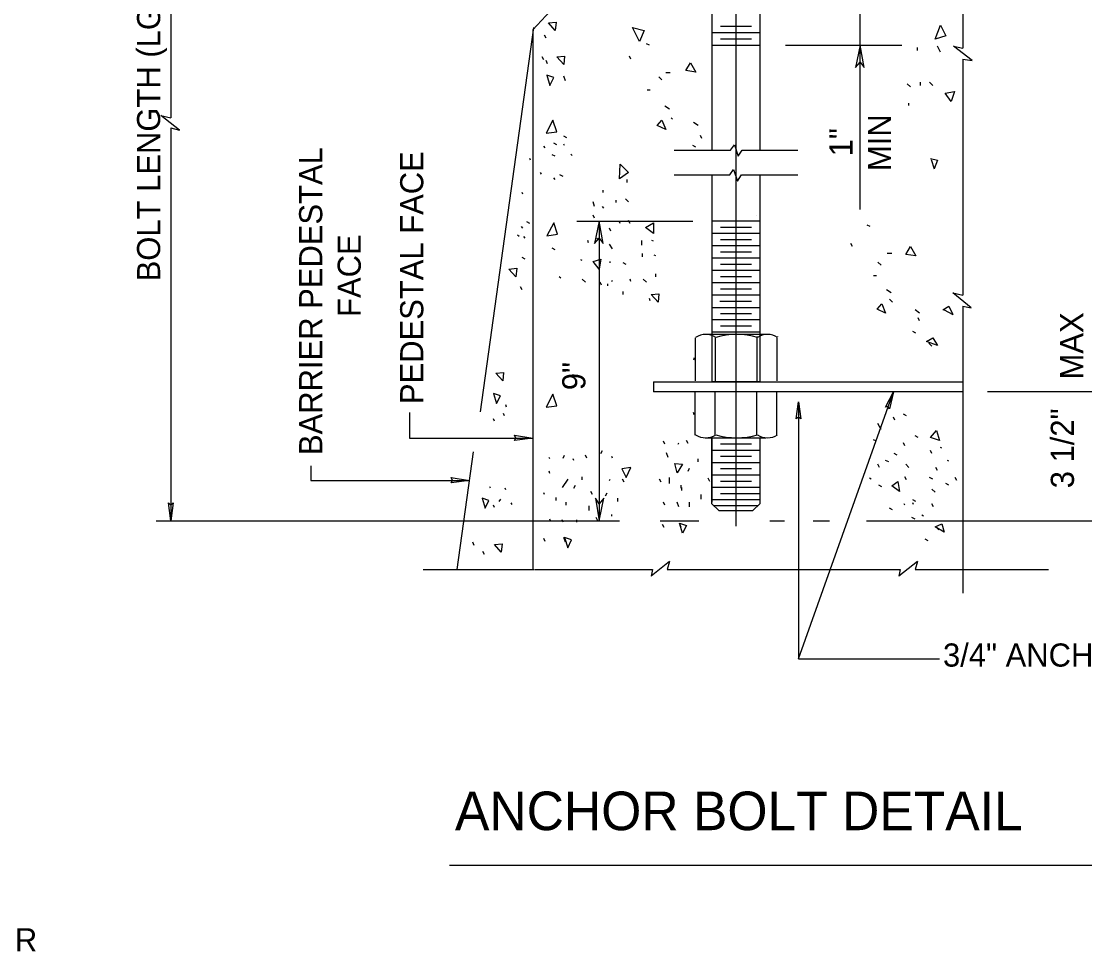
# Model space of a CAD drawing. Extents: x -3 to 26050223, y 0 to 12035012.
# Drawn here: x 15.59 to 27.07, y 26.48 to 36.52 of the extents above; entities that cross this region are included whole.
import ezdxf

# ---------------------------------------------------------------- set-up
doc = ezdxf.new("R2010")
doc.units = 0
for name, color, linetype in [('1', 7, 'Continuous'), ('2', 7, 'Continuous'), ('39', 7, 'Continuous')]:
    doc.layers.add(name, color=color, linetype=linetype)

msp = doc.modelspace()

# ---------------------------------------------------------------- linework, layer by layer
at = {"layer": '1'}
for p, q in [((23.308, 39.917), (23.308, 31.075)), ((23.05, 37.15), (23.05, 35.133)), ((23.567, 37.142), (23.567, 35.133)), ((21.117, 36.433), (21.35, 36.683)), ((20.55, 32.308), (21.125, 36.458)), ((21.117, 36.433), (21.117, 30.608)), ((23.533, 36.267), (23.533, 36.267)), ((23.05, 34.867), (23.05, 32.633)), ((23.567, 34.867), (23.567, 32.633)), ((22.867, 33.108), (22.867, 32.642)), ((23.633, 33.142), (22.975, 33.142)), ((23.633, 33.142), (22.975, 33.142)), ((23.083, 33.108), (23.083, 32.642)), ((23.533, 33.108), (23.533, 32.642)), ((23.75, 33.108), (23.75, 32.642)), ((22.417, 32.633), (22.417, 32.525)), ((22.417, 32.633), (25.758, 32.633)), ((25.758, 32.525), (22.417, 32.525)), ((22.867, 32.058), (22.867, 32.525)), ((23.083, 32.058), (23.083, 32.525)), ((23.533, 32.058), (23.533, 32.525)), ((23.75, 32.058), (23.75, 32.525)), ((23.633, 32.025), (22.975, 32.025)), ((23.633, 32.025), (22.975, 32.025)), ((23.05, 31.317), (23.05, 32.025)), ((23.567, 32.025), (23.567, 31.317)), ((20.3, 30.608), (20.475, 31.875)), ((23.05, 31.317), (23.125, 31.242)), ((23.542, 31.292), (23.075, 31.292)), ((23.125, 31.242), (23.492, 31.242)), ((23.567, 31.317), (23.492, 31.242)), ((20.217, 27.413), (27.25, 27.413))]:
    msp.add_line(p, q, dxfattribs=at)
for points in [[(24.65, 36.267), (24.6, 36.025), (24.65, 36.083), (24.692, 36.025)], [(21.833, 34.367), (21.783, 34.125), (21.833, 34.183), (21.875, 34.125)], [(21.833, 34.367), (21.783, 34.125), (21.833, 34.183), (21.875, 34.125)], [(20.933, 32.025), (20.917, 32.058), (21.117, 32.025), (20.917, 32)], [(20.25, 31.567), (20.233, 31.6), (20.433, 31.567), (20.233, 31.542)], [(21.833, 31.133), (21.883, 31.375), (21.833, 31.317), (21.792, 31.375)]]:
    msp.add_lwpolyline(points, close=True, dxfattribs=at)
for centre, radius, start, end in [((22.982, 32.953), 0.192, 55.6284, 124.4174), ((22.982, 32.953), 0.192, 55.6284, 90), ((23.316, 32.368), 0.776, 73.1289, 106.8539), ((23.316, 32.368), 0.776, 73.1289, 106.8539), ((23.649, 32.953), 0.192, 55.5826, 124.3065), ((23.649, 32.953), 0.192, 90, 124.3065), ((23.307, 32.045), 1.1, 77.7537, 77.7623), ((23.991, 32.045), 1.1, 102.2377, 102.2463), ((22.982, 32.22), 0.192, 235.5826, 304.3716), ((22.982, 32.22), 0.192, 270, 304.3716), ((23.316, 32.804), 0.776, 253.1461, 286.8711), ((23.316, 32.804), 0.776, 253.1461, 286.8711), ((23.649, 32.22), 0.192, 235.6935, 304.4174), ((23.649, 32.22), 0.192, 235.6935, 270), ((23.307, 33.128), 1.1, 282.2377, 282.2463), ((23.991, 33.128), 1.1, 257.7537, 257.7623)]:
    msp.add_arc(centre, radius, start, end, dxfattribs=at)
at = {"layer": '2'}
for p, q in [((17.208, 39.683), (17.208, 35.483)), ((25.758, 36.983), (25.758, 36.233)), ((24.65, 36.267), (24.65, 36.683)), ((21.283, 36.508), (21.367, 36.517)), ((21.367, 36.517), (21.358, 36.425)), ((21.358, 36.425), (21.283, 36.508)), ((22.192, 36.458), (22.317, 36.425)), ((22.267, 36.308), (22.192, 36.458)), ((22.317, 36.425), (22.267, 36.308)), ((23.567, 36.4), (23.05, 36.4)), ((23.475, 36.467), (23.142, 36.467)), ((23.533, 36.4), (23.533, 36.4)), ((25.458, 36.333), (25.517, 36.483)), ((25.517, 36.483), (25.575, 36.367)), ((21.258, 36.342), (21.242, 36.375)), ((23.475, 36.333), (23.142, 36.333)), ((25.575, 36.367), (25.458, 36.333)), ((22.375, 36.267), (22.342, 36.283)), ((23.05, 36.267), (23.567, 36.267)), ((23.842, 36.267), (25.1, 36.267)), ((24.65, 34.492), (24.65, 36.267)), ((25.267, 36.208), (25.267, 36.242)), ((25.517, 36.192), (25.483, 36.258)), ((25.858, 36.1), (25.658, 36.258)), ((25.658, 36.258), (25.758, 36.233)), ((25.858, 36.1), (25.658, 36.258)), ((25.658, 36.258), (25.758, 36.233)), ((21.233, 36.108), (21.217, 36.142)), ((21.275, 36.067), (21.258, 36.1)), ((21.375, 36.142), (21.458, 36.15)), ((21.45, 36.058), (21.375, 36.142)), ((21.458, 36.15), (21.45, 36.058)), ((22.175, 36.117), (22.158, 36.15)), ((22.767, 35.992), (22.817, 36.075)), ((22.817, 36.075), (22.875, 35.975)), ((25.758, 36.117), (25.758, 33.567)), ((25.758, 36.117), (25.858, 36.1)), ((21.267, 35.942), (21.3, 35.833)), ((21.342, 35.917), (21.267, 35.942)), ((22.6, 35.967), (22.55, 35.967)), ((22.875, 35.975), (22.767, 35.992)), ((21.3, 35.833), (21.342, 35.917)), ((21.467, 35.883), (21.45, 35.933)), ((22.508, 35.892), (22.475, 35.925)), ((25.192, 35.817), (25.158, 35.85)), ((25.3, 35.833), (25.3, 35.867)), ((25.433, 35.833), (25.4, 35.867)), ((22.383, 35.783), (22.35, 35.783)), ((25.567, 35.75), (25.667, 35.767)), ((25.633, 35.658), (25.567, 35.75)), ((25.667, 35.767), (25.633, 35.658)), ((22.592, 35.575), (22.542, 35.608)), ((25.175, 35.617), (25.175, 35.642)), ((17.3, 35.35), (17.1, 35.508)), ((17.1, 35.508), (17.208, 35.483)), ((22.625, 35.467), (22.608, 35.483)), ((17.208, 35.375), (17.208, 31.133)), ((17.208, 35.375), (17.3, 35.35)), ((21.333, 35.458), (21.258, 35.317)), ((21.375, 35.333), (21.333, 35.458)), ((22.458, 35.4), (22.508, 35.458)), ((22.55, 35.358), (22.458, 35.4)), ((22.508, 35.458), (22.55, 35.358)), ((22.9, 35.4), (22.85, 35.433)), ((21.258, 35.317), (21.375, 35.333)), ((21.483, 35.267), (21.45, 35.283)), ((22.942, 35.258), (22.925, 35.292)), ((21.25, 35.158), (21.233, 35.175)), ((21.375, 35.192), (21.342, 35.208)), ((21.458, 35.183), (21.45, 35.2)), ((22.875, 35.167), (22.842, 35.183)), ((23.25, 35.133), (23.292, 35.192)), ((23.292, 35.192), (23.333, 35.067)), ((21.092, 35.025), (21.083, 35.042)), ((21.358, 35.067), (21.325, 35.083)), ((21.542, 35.075), (21.525, 35.092)), ((22.642, 35.133), (23.25, 35.133)), ((23.333, 35.067), (23.375, 35.133)), ((23.375, 35.133), (23.975, 35.133)), ((25.408, 35.042), (25.483, 35.025)), ((25.417, 35.033), (25.45, 34.933)), ((25.483, 35.025), (25.45, 34.933)), ((22.05, 34.825), (22.058, 34.983)), ((22.058, 34.983), (22.15, 34.892)), ((23.242, 34.867), (23.283, 34.925)), ((23.283, 34.925), (23.325, 34.8)), ((21.208, 34.875), (21.2, 34.892)), ((21.358, 34.817), (21.342, 34.833)), ((21.442, 34.85), (21.408, 34.867)), ((22.15, 34.892), (22.05, 34.825)), ((22.133, 34.783), (22.133, 34.817)), ((22.642, 34.867), (23.242, 34.867)), ((23.325, 34.8), (23.367, 34.867)), ((23.367, 34.867), (23.975, 34.867)), ((21.875, 34.675), (21.875, 34.7)), ((21.008, 34.658), (21, 34.675)), ((21.783, 34.525), (21.767, 34.575)), ((22.017, 34.567), (22.017, 34.592)), ((22.15, 34.575), (22.117, 34.608)), ((21.883, 34.508), (21.867, 34.525)), ((21.083, 34.342), (21.05, 34.358)), ((21.342, 34.35), (21.267, 34.208)), ((21.383, 34.225), (21.342, 34.35)), ((21.592, 34.367), (22.842, 34.367)), ((21.783, 34.4), (21.767, 34.433)), ((21.833, 34.367), (21.833, 31.133)), ((22.058, 34.342), (22.05, 34.358)), ((22.167, 34.342), (22.15, 34.375)), ((22.333, 34.3), (22.417, 34.35)), ((22.417, 34.35), (22.417, 34.233)), ((23.567, 34.367), (23.05, 34.367)), ((23.533, 34.433), (23.533, 34.433)), ((23.533, 34.433), (23.533, 34.433)), ((23.533, 34.367), (23.533, 34.367)), ((23.533, 34.367), (23.533, 34.367)), ((21.008, 34.292), (20.992, 34.308)), ((21.267, 34.208), (21.383, 34.225)), ((21.958, 34.258), (21.942, 34.292)), ((22.417, 34.233), (22.333, 34.3)), ((23.567, 34.233), (23.05, 34.233)), ((23.475, 34.3), (23.142, 34.3)), ((23.533, 34.233), (23.533, 34.233)), ((24.758, 34.308), (24.725, 34.325)), ((20.967, 34.2), (20.95, 34.217)), ((21.033, 34.183), (21.017, 34.2)), ((21.717, 34.133), (21.708, 34.158)), ((21.825, 34.167), (21.808, 34.183)), ((21.975, 34.067), (21.942, 34.117)), ((22.292, 34.108), (22.292, 34.158)), ((22.417, 34.15), (22.4, 34.158)), ((23.475, 34.167), (23.142, 34.167)), ((24.567, 34.092), (24.55, 34.125)), ((21.358, 34.058), (21.325, 34.075)), ((22.3, 33.983), (22.3, 34.017)), ((22.442, 33.992), (22.425, 34)), ((23.567, 34.1), (23.05, 34.1)), ((23.475, 34.033), (23.142, 34.033)), ((23.533, 34.1), (23.533, 34.1)), ((24.992, 34.017), (24.942, 34.017)), ((25.142, 34.008), (25.192, 34.092)), ((25.25, 33.992), (25.142, 34.008)), ((25.192, 34.092), (25.25, 33.992)), ((21.033, 33.958), (21, 33.975)), ((21.65, 33.942), (21.633, 33.95)), ((21.767, 33.933), (21.85, 33.958)), ((21.833, 33.85), (21.767, 33.933)), ((21.85, 33.958), (21.833, 33.85)), ((21.95, 33.917), (21.95, 33.933)), ((22.125, 33.9), (22.092, 33.917)), ((23.567, 33.967), (23.05, 33.967)), ((23.567, 33.967), (23.05, 33.967)), ((23.475, 33.9), (23.142, 33.9)), ((23.533, 33.967), (23.533, 33.967)), ((23.533, 33.967), (23.533, 33.967)), ((24.875, 33.892), (24.842, 33.925)), ((20.858, 33.85), (20.942, 33.858)), ((20.933, 33.767), (20.858, 33.85)), ((20.942, 33.858), (20.933, 33.767)), ((21.417, 33.75), (21.4, 33.767)), ((22.442, 33.767), (22.442, 33.8)), ((23.567, 33.833), (23.05, 33.833)), ((23.475, 33.767), (23.142, 33.767)), ((23.533, 33.833), (23.533, 33.833)), ((24.825, 33.775), (24.792, 33.775)), ((21, 33.625), (20.983, 33.658)), ((21.683, 33.708), (21.65, 33.742)), ((21.858, 33.675), (21.842, 33.708)), ((21.925, 33.667), (21.925, 33.692)), ((21.975, 33.717), (21.967, 33.725)), ((22.175, 33.717), (22.167, 33.742)), ((22.342, 33.708), (22.308, 33.742)), ((23.567, 33.7), (23.05, 33.7)), ((23.533, 33.7), (23.533, 33.7)), ((22.092, 33.575), (22.092, 33.608)), ((22.383, 33.508), (22.375, 33.533)), ((22.392, 33.575), (22.475, 33.583)), ((22.467, 33.492), (22.392, 33.575)), ((22.475, 33.583), (22.467, 33.492)), ((23.567, 33.567), (23.05, 33.567)), ((23.475, 33.633), (23.142, 33.633)), ((23.533, 33.567), (23.533, 33.567)), ((24.983, 33.592), (24.933, 33.625)), ((25.85, 33.433), (25.65, 33.592)), ((25.65, 33.592), (25.758, 33.567)), ((23.567, 33.433), (23.05, 33.433)), ((23.467, 33.5), (23.133, 33.5)), ((23.475, 33.5), (23.142, 33.5)), ((23.533, 33.433), (23.533, 33.433)), ((23.533, 33.433), (23.533, 33.433)), ((24.833, 33.417), (24.883, 33.475)), ((24.925, 33.375), (24.833, 33.417)), ((24.883, 33.475), (24.925, 33.375)), ((25, 33.492), (24.967, 33.525)), ((25.542, 33.408), (25.608, 33.45)), ((25.608, 33.45), (25.65, 33.358)), ((25.758, 33.45), (25.758, 30.35)), ((25.758, 33.45), (25.85, 33.433)), ((23.567, 33.3), (23.05, 33.3)), ((23.475, 33.367), (23.142, 33.367)), ((23.533, 33.3), (23.533, 33.3)), ((25.292, 33.375), (25.242, 33.408)), ((25.292, 33.292), (25.275, 33.325)), ((25.558, 33.408), (25.65, 33.358)), ((23.475, 33.233), (23.142, 33.233)), ((23.567, 33.167), (23.05, 33.167)), ((23.533, 33.167), (23.533, 33.167)), ((23.533, 33.142), (23.533, 33.142)), ((25.25, 33.158), (25.217, 33.175)), ((25.367, 33.067), (25.433, 33.108)), ((25.433, 33.108), (25.483, 33.025)), ((23.533, 33.033), (23.533, 33.033)), ((23.533, 33.033), (23.533, 33.033)), ((25.483, 33.025), (25.367, 33.067)), ((25.425, 33.017), (25.392, 33.05)), ((22.858, 32.892), (22.85, 32.867)), ((23.533, 32.9), (23.533, 32.9)), ((20.717, 32.725), (20.8, 32.733)), ((20.792, 32.642), (20.717, 32.725)), ((20.8, 32.733), (20.792, 32.642)), ((23.533, 32.767), (23.533, 32.767)), ((23.567, 32.633), (23.05, 32.633)), ((23.533, 32.633), (23.533, 32.633)), ((20.692, 32.508), (20.725, 32.4)), ((20.767, 32.483), (20.692, 32.508)), ((21.333, 32.5), (21.258, 32.358)), ((21.375, 32.375), (21.333, 32.5)), ((23.983, 29.642), (25.008, 32.525)), ((27.283, 32.525), (26.025, 32.525)), ((20.725, 32.4), (20.767, 32.483)), ((20.833, 32.358), (20.825, 32.383)), ((23.983, 32.417), (23.983, 29.642)), ((19.783, 32.3), (19.783, 32.025)), ((20.808, 32.267), (20.8, 32.292)), ((21.258, 32.358), (21.375, 32.375)), ((22.858, 32.275), (22.85, 32.3)), ((25.15, 32.267), (25.117, 32.283)), ((20.7, 32.208), (20.692, 32.233)), ((24.875, 32.117), (24.842, 32.183)), ((25.025, 32.217), (25.008, 32.25)), ((25.275, 32.033), (25.242, 32.05)), ((25.408, 32.033), (25.475, 32.108)), ((25.475, 32.108), (25.508, 32)), ((19.783, 32.025), (21.117, 32.025)), ((22.542, 31.958), (22.525, 31.992)), ((22.683, 31.958), (22.692, 31.975)), ((22.792, 31.967), (22.775, 32)), ((23.05, 32.025), (23.05, 31.333)), ((23.475, 31.958), (23.142, 31.958)), ((23.533, 32.025), (23.533, 32.025)), ((24.825, 31.992), (24.792, 32.008)), ((25.133, 31.942), (25.117, 31.975)), ((25.508, 32), (25.408, 32.033)), ((25.533, 31.917), (25.517, 31.925)), ((21.3, 31.8), (21.292, 31.817)), ((21.442, 31.808), (21.458, 31.842)), ((21.7, 31.808), (21.683, 31.842)), ((21.85, 31.858), (21.867, 31.892)), ((21.975, 31.808), (21.967, 31.825)), ((22.575, 31.817), (22.558, 31.867)), ((23.567, 31.892), (23.05, 31.892)), ((23.475, 31.825), (23.142, 31.825)), ((23.533, 31.892), (23.533, 31.892)), ((25.05, 31.842), (25.017, 31.858)), ((25.425, 31.858), (25.408, 31.892)), ((18.717, 31.725), (18.717, 31.567)), ((21.558, 31.783), (21.55, 31.8)), ((22.175, 31.708), (22.075, 31.692)), ((22.175, 31.708), (22.075, 31.692)), ((22.075, 31.692), (22.125, 31.6)), ((22.075, 31.692), (22.125, 31.6)), ((22.125, 31.6), (22.175, 31.708)), ((22.125, 31.6), (22.175, 31.708)), ((22.125, 31.6), (22.175, 31.708)), ((22.65, 31.75), (22.733, 31.742)), ((22.675, 31.65), (22.65, 31.75)), ((22.733, 31.742), (22.675, 31.65)), ((22.792, 31.667), (22.808, 31.7)), ((22.9, 31.767), (22.9, 31.8)), ((23.567, 31.758), (23.05, 31.758)), ((23.475, 31.692), (23.142, 31.692)), ((23.533, 31.758), (23.533, 31.758)), ((24.858, 31.708), (24.842, 31.742)), ((24.958, 31.767), (24.925, 31.783)), ((25.175, 31.708), (25.142, 31.742)), ((25.483, 31.675), (25.467, 31.708)), ((25.608, 31.775), (25.592, 31.783)), ((21.3, 31.642), (21.292, 31.667)), ((21.492, 31.583), (21.433, 31.492)), ((21.65, 31.575), (21.65, 31.608)), ((21.942, 31.567), (21.95, 31.583)), ((22.1, 31.55), (22.083, 31.583)), ((22.5, 31.55), (22.483, 31.583)), ((22.592, 31.533), (22.592, 31.6)), ((23.025, 31.558), (23.008, 31.592)), ((23.567, 31.625), (23.05, 31.625)), ((23.533, 31.625), (23.533, 31.625)), ((24.767, 31.583), (24.75, 31.592)), ((25.15, 31.575), (25.133, 31.608)), ((25.433, 31.583), (25.4, 31.6)), ((25.692, 31.567), (25.675, 31.6)), ((18.717, 31.567), (20.433, 31.567)), ((20.658, 31.483), (20.65, 31.5)), ((20.825, 31.467), (20.817, 31.483)), ((21.558, 31.483), (21.575, 31.517)), ((22.717, 31.483), (22.717, 31.517)), ((22.725, 31.458), (22.725, 31.492)), ((23.567, 31.492), (23.05, 31.492)), ((23.475, 31.558), (23.142, 31.558)), ((23.533, 31.492), (23.533, 31.492)), ((24.883, 31.5), (24.85, 31.517)), ((24.992, 31.508), (25.058, 31.558)), ((25.075, 31.45), (24.992, 31.508)), ((25.058, 31.558), (25.075, 31.45)), ((25.458, 31.442), (25.425, 31.475)), ((25.608, 31.517), (25.575, 31.533)), ((20.567, 31.375), (20.6, 31.267)), ((20.642, 31.35), (20.567, 31.375)), ((20.6, 31.267), (20.642, 31.35)), ((20.767, 31.367), (20.75, 31.342)), ((21.242, 31.417), (21.233, 31.433)), ((21.367, 31.35), (21.367, 31.383)), ((21.758, 31.417), (21.742, 31.45)), ((21.9, 31.4), (21.917, 31.433)), ((22.033, 31.342), (22.033, 31.375)), ((22.933, 31.367), (22.933, 31.417)), ((23.567, 31.358), (23.05, 31.358)), ((23.567, 31.425), (23.142, 31.425)), ((23.533, 31.425), (23.533, 31.425)), ((23.533, 31.358), (23.533, 31.358)), ((25.25, 31.342), (25.217, 31.358)), ((20.7, 31.275), (20.692, 31.3)), ((20.892, 31.308), (20.883, 31.325)), ((21.475, 31.3), (21.475, 31.333)), ((21.725, 31.242), (21.725, 31.292)), ((22.542, 31.3), (22.525, 31.333)), ((22.692, 31.283), (22.675, 31.333)), ((22.808, 31.283), (22.808, 31.333)), ((23.125, 31.242), (23.483, 31.242)), ((23.133, 31.242), (23.45, 31.242)), ((23.533, 31.292), (23.533, 31.292)), ((25, 31.25), (24.967, 31.267)), ((25.133, 31.3), (25.125, 31.317)), ((25.225, 31.308), (25.217, 31.325)), ((25.442, 31.283), (25.425, 31.317)), ((17.05, 31.133), (22.05, 31.133)), ((21.308, 31.133), (21.3, 31.15)), ((21.442, 31.117), (21.433, 31.142)), ((21.592, 31.117), (21.592, 31.142)), ((21.817, 31.133), (21.8, 31.167)), ((21.967, 31.183), (21.967, 31.2)), ((22.492, 31.133), (22.908, 31.133)), ((23.675, 31.133), (23.833, 31.133)), ((24.142, 31.133), (24.317, 31.133)), ((24.717, 31.133), (27.267, 31.133)), ((25.242, 31.15), (25.208, 31.167)), ((25.333, 31.183), (25.317, 31.192)), ((22.533, 31.058), (22.517, 31.092)), ((22.7, 31.108), (22.775, 31.083)), ((22.733, 31), (22.7, 31.108)), ((22.717, 31.058), (22.7, 31.108)), ((22.775, 31.083), (22.733, 31)), ((25.458, 31.067), (25.533, 31.1)), ((25.558, 31.008), (25.458, 31.067)), ((25.5, 31.033), (25.467, 31.067)), ((25.533, 31.1), (25.558, 31.008)), ((20.483, 30.867), (20.467, 30.9)), ((21.25, 30.908), (21.233, 30.942)), ((21.467, 30.9), (21.45, 30.95)), ((21.458, 30.95), (21.492, 30.842)), ((21.533, 30.925), (21.458, 30.95)), ((21.492, 30.842), (21.533, 30.925)), ((25.383, 30.917), (25.35, 30.933)), ((20.592, 30.767), (20.575, 30.8)), ((20.7, 30.875), (20.783, 30.883)), ((20.775, 30.792), (20.7, 30.875)), ((20.783, 30.883), (20.775, 30.792)), ((22.592, 30.692), (22.392, 30.533)), ((22.592, 30.692), (22.567, 30.608)), ((25.267, 30.692), (25.067, 30.533)), ((25.267, 30.692), (25.242, 30.608)), ((19.933, 30.608), (21.133, 30.608)), ((21.142, 30.608), (22.408, 30.608)), ((22.408, 30.608), (22.392, 30.533)), ((22.567, 30.608), (25.083, 30.608)), ((25.083, 30.608), (25.067, 30.533)), ((25.242, 30.608), (25.758, 30.608)), ((25.758, 30.608), (26.683, 30.608)), ((23.983, 29.642), (25.508, 29.642))]:
    msp.add_line(p, q, dxfattribs=at)
for points in [[(24.925, 32.358), (25.008, 32.525), (24.967, 32.342), (24.95, 32.367)], [(23.958, 32.233), (23.983, 32.417), (24.008, 32.233), (23.983, 32.25)], [(17.233, 31.325), (17.208, 31.133), (17.183, 31.325), (17.208, 31.3)]]:
    msp.add_lwpolyline(points, close=True, dxfattribs=at)

# ---------------------------------------------------------------- texts
msp.add_text('ANCHOR BOLT DETAIL', height=0.41665, dxfattribs=at).set_placement((20.275, 27.792))
at = {"layer": '39'}
for s, height, p in [('BOLT LENGTH (LGTH)', 0.25, (17.092, 33.717)), ('MIN', 0.2499, (24.983, 34.908)), ('1"', 0.2499, (24.567, 35.067)), ('BARRIER PEDESTAL ', 0.2499, (18.842, 31.842)), ('PEDESTAL FACE', 0.2499, (19.933, 32.392)), ('FACE', 0.2499, (19.258, 33.333)), ('MAX', 0.25, (27.058, 32.658)), ('9"', 0.25, (21.683, 32.542)), ('3 1/2"', 0.25, (26.958, 31.483))]:
    msp.add_text(s, height=height, rotation=90, dxfattribs=at).set_placement(p)
for s, p in [('3/4" ANCHOR PLATES', (25.544, 29.558)), (' 3 / 4" ANCHOR', (13.361, 26.483))]:
    msp.add_text(s, height=0.25, dxfattribs=at).set_placement(p)

doc.saveas('drawing.dxf')
